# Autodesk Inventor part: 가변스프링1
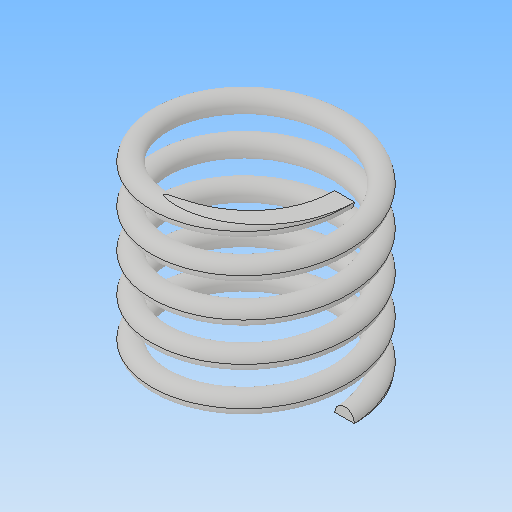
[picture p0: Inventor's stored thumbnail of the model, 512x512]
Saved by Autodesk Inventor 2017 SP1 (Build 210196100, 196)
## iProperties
Part Number: 가변스프링1
Material: 일반
Document SubType Name: Modeling
Designer: MRC
Density: 1 g/cm^3
Appearance: 기본값
Mass: 0.870346 g
Surface Area: 17.6923 cm^2
Volume: 0.870346 cm^3
Author: MRC
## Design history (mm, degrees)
sketch "스케치1"
  geometry: L1 (0, 0)-(0, 19.5); L2 (0, 0)-(9, 0); L3 (0, 19.5)-(9, 19.5); C1 r 1 at (9, 0)
  constraints: 6 end point, 1 centre point, 1 coincident, 1 parallel, 1 perpendicular, 1 vertical
  dimensions: "d0" = 19.5 distance of L1.start L1.end (derived); "d1" = 9 distance of L1.start L2.end; "d2" = 9 distance of L1.end L3.end; "d3" = 2 diameter of C1
feature "코일1" sketch "스케치1" pitch "d4" = 10; turns "d6" = 5; dims "d5" = 19.5 (= d0), "d7" = 0, angle "d8" = 90 deg, angle "d9" = 90 deg, "d10" = 0, "d11" = 0
sketch "스케치2"
  geometry: L1 (19.5, 20)-(0, 20); L2 (0, 20)-(0, -20); L3 (0, -20)-(19.5, -20); L4 (19.5, -20)-(19.5, 20); 2 further points
  constraints: 8 end point, 2 parallel, 1 coincident, 1 horizontal, 1 midpoint, 1 perpendicular
  dimensions: "d12" = 40 distance of L3.end L1.start; "d13" = 19.5 distance of L2.end L3.end (= d0)
extrude "돌출1" sketch "스케치2" stored distance "d14" = 0; taper "d15" = 0 deg
node "솔리드1"
